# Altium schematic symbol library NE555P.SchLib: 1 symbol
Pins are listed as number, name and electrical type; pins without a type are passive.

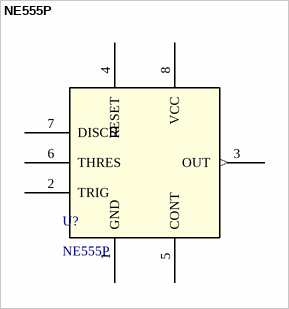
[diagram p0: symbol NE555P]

## NE555P
designator U?
NE555P Timer; Vendor: Texas Instruments; Built_By: EMA_UL_Team; C: Copyright (C) 2015 Accelerated Designs. All rights reserved
footprint NE555P
pins: 1 GND (power), 2 TRIG, 3 OUT (out), 4 RESET, 5 CONT, 6 THRES, 7 DISCH, 8 VCC (power)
